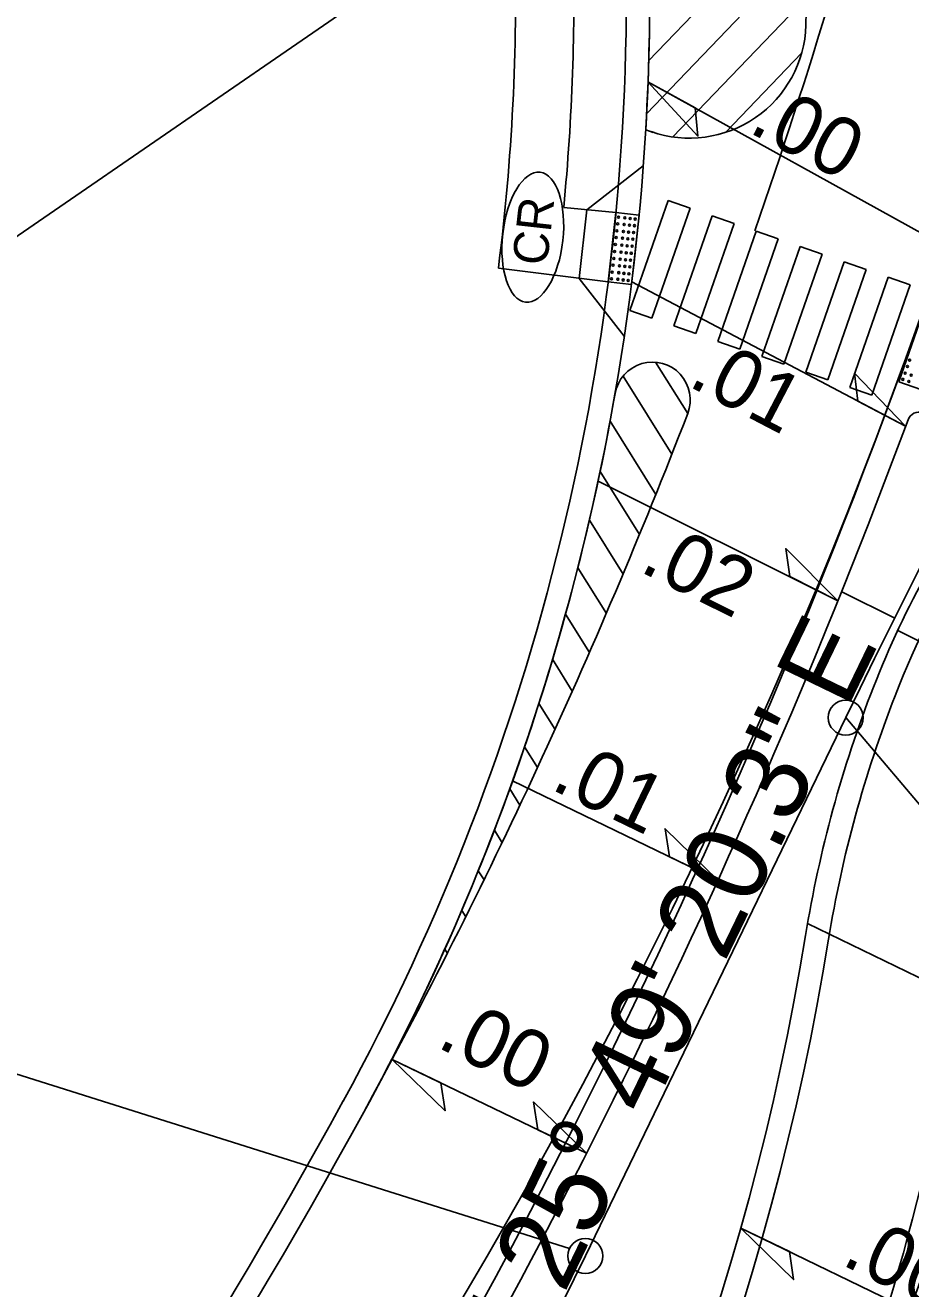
# Model space of a CAD drawing. Extents: x 2010838 to 2015151, y 441905 to 447792.
# Drawn here: x 2011817.1 to 2011893.1, y 444822.7 to 444931.1 of the extents above; entities that cross this region are included whole.
import ezdxf

# ---------------------------------------------------------------- set-up
doc = ezdxf.new("R2010")
doc.units = 0
for name, color, linetype in [('A-Wall-Blow', 7, 'Continuous'), ('A-Wall-Comp', 7, 'Continuous'), ('C-Alignment Geometry', 7, 'Continuous'), ('C-Building', 7, 'Continuous'), ('C-CURB STOPS', 7, 'Continuous'), ('CLRD', 7, 'Continuous'), ('Cont-2-Lidar', 7, 'Continuous'), ('Default_10ft_LIDAR_Contou', 7, 'Continuous'), ('HATCH', 7, 'Continuous'), ('S-overhead electric', 7, 'Continuous'), ('TEXT-LG', 7, 'Continuous'), ('TEXT-MED', 7, 'Continuous'), ('X4', 7, 'Continuous')]:
    doc.layers.add(name, color=color, linetype=linetype)

msp = doc.modelspace()

# ---------------------------------------------------------------- linework, layer by layer
at = {"layer": 'A-Wall-Blow'}
for p, q in [((2011897.95, 444911.04), (2011870.53, 444926.22)), ((2011892.64, 444896.68), (2011869.14, 444909.05)), ((2011866.25, 444891.98), (2011886.83, 444881.71)), ((2011891.96, 444879.15), (2011923.13, 444863.6)), ((2011858.92, 444866.26), (2011876.53, 444857.74)), ((2011884.23, 444854.02), (2011912.5, 444840.34)), ((2011848.59, 444842.38), (2011865.25, 444834.32)), ((2011878.5, 444827.91), (2011902.65, 444816.22))]:
    msp.add_line(p, q, dxfattribs=at)
at = {"layer": 'A-Wall-Comp'}
for points in [[(2011870.53, 444926.22), (2011874.82, 444921.56), (2011874.58, 444923.98)], [(2011892.64, 444896.68), (2011888.26, 444901.24), (2011888.55, 444898.83)], [(2011886.83, 444881.71), (2011882.35, 444886.18), (2011882.69, 444883.78)], [(2011876.53, 444857.74), (2011872, 444862.16), (2011872.37, 444859.76)], [(2011848.59, 444842.38), (2011853.12, 444837.97), (2011852.75, 444840.36)], [(2011865.25, 444834.32), (2011860.72, 444838.73), (2011861.09, 444836.33)], [(2011878.5, 444827.91), (2011883.03, 444823.49), (2011882.66, 444825.89)]]:
    msp.add_lwpolyline(points, close=True, dxfattribs=at)
at = {"layer": 'C-Alignment Geometry'}
for p, q in [((2011870.59, 444928.01), (2011882.99, 444940.93)), ((2011870.41, 444923.48), (2011883.72, 444937.35)), ((2011872.66, 444921.49), (2011884.08, 444933.39)), ((2011877.2, 444921.89), (2011883.71, 444928.67)), ((2011870.34, 444922.11), (2011870.98, 444921.88)), ((2011873.94, 444897.76), (2011871.19, 444902.17)), ((2011872.58, 444894.27), (2011868.39, 444900.98)), ((2011871.2, 444890.82), (2011867.28, 444897.1)), ((2011869.81, 444887.39), (2011866.43, 444892.8)), ((2011868.39, 444883.99), (2011865.5, 444888.62)), ((2011866.96, 444880.62), (2011864.51, 444884.54)), ((2011865.51, 444877.28), (2011863.46, 444880.57)), ((2011864.04, 444873.96), (2011862.34, 444876.69)), ((2011862.56, 444870.67), (2011861.17, 444872.9)), ((2011861.06, 444867.41), (2011859.95, 444869.19)), ((2011859.55, 444864.17), (2011858.67, 444865.57)), ((2011858.01, 444860.96), (2011857.35, 444862.03)), ((2011856.47, 444857.77), (2011855.97, 444858.56)), ((2011854.9, 444854.61), (2011854.56, 444855.16)), ((2011853.33, 444851.47), (2011853.1, 444851.84))]:
    msp.add_line(p, q, dxfattribs=at)
for centre, radius, start, end in [((2011849.1, 444932.2), 35, 358.1503, 56.9341), ((2011670.68, 444933.83), 200, 356.639, 1.3736), ((2011874.09, 444931.39), 10, 250.8378, 358.1503), ((2011870.91, 444898.93), 3.25, 338.8939, 170.1114), ((2011670.68, 444933.83), 200, 331.3204, 350.1114), ((2011407.48, 445077.81), 500, 331.3204, 338.8939), ((2011610.55, 444921.96), 300, 327.6618, 346.3627), ((2011662.93, 444888.8), 238, 327.6618, 350.8051)]:
    msp.add_arc(centre, radius, start, end, dxfattribs=at)
at = {"layer": 'C-Building'}
msp.add_line((2011891.7, 444880.22), (2011887.22, 444882.46), dxfattribs=at)
at = {"layer": 'C-CURB STOPS'}
for centre, radius, start, end in [((2011893.78, 444896.89), 1, 70.782, 159.5904), ((2011328.64, 445107.17), 602, 316.13249, 339.59044), ((2011966.23, 444844.41), 82, 143.1452, 158.6236), ((2011986.72, 444836.39), 104, 158.6236, 170.8051), ((2011662.93, 444888.8), 224, 304.0474, 350.8051)]:
    msp.add_arc(centre, radius, start, end, dxfattribs=at)
at = {"layer": 'CLRD'}
msp.add_line((2011865.16, 444825.52), (2011887.5, 444871.69), dxfattribs=at)
for centre, radius, start, end in [((2012535.6, 444558.07), 720, 139.84446, 154.1777), ((2011505.1, 444999.75), 400, 314.169, 334.1777)]:
    msp.add_arc(centre, radius, start, end, dxfattribs=at)
at = {"layer": 'Default_10ft_LIDAR_Contou'}
for p, q in [((2011917.67, 444982.63), (2011806.71, 444906.31)), ((2011863.81, 444826.17), (2011708.02, 444875.19)), ((2011887.5, 444871.69), (2011991.38, 444748.94))]:
    msp.add_line(p, q, dxfattribs=at)
for centre in [(2011887.5, 444871.69), (2011865.16, 444825.52)]:
    msp.add_circle(centre, 1.5, dxfattribs=at)
at = {"layer": 'HATCH'}
for p, q in [((2011872.26, 444916.04), (2011868.97, 444906.6)), ((2011874.15, 444915.38), (2011872.26, 444916.04)), ((2011870.86, 444905.94), (2011874.15, 444915.38)), ((2011876.04, 444914.72), (2011872.75, 444905.28)), ((2011874.63, 444904.62), (2011877.93, 444914.06)), ((2011877.93, 444914.06), (2011876.04, 444914.72)), ((2011879.81, 444913.41), (2011876.52, 444903.96)), ((2011878.41, 444903.3), (2011881.7, 444912.75)), ((2011881.7, 444912.75), (2011879.81, 444913.41)), ((2011883.59, 444912.09), (2011880.3, 444902.65)), ((2011885.48, 444911.43), (2011883.59, 444912.09)), ((2011882.19, 444901.99), (2011885.48, 444911.43)), ((2011887.37, 444910.77), (2011884.08, 444901.33)), ((2011889.26, 444910.11), (2011887.37, 444910.77)), ((2011885.97, 444900.67), (2011889.26, 444910.11)), ((2011891.15, 444909.46), (2011887.85, 444900.01)), ((2011893.03, 444908.8), (2011891.15, 444909.46)), ((2011889.74, 444899.35), (2011893.03, 444908.8)), ((2011868.97, 444906.6), (2011870.86, 444905.94)), ((2011872.75, 444905.28), (2011874.63, 444904.62)), ((2011876.52, 444903.96), (2011878.41, 444903.3)), ((2011880.3, 444902.65), (2011882.19, 444901.99)), ((2011884.08, 444901.33), (2011885.97, 444900.67)), ((2011887.85, 444900.01), (2011889.74, 444899.35))]:
    msp.add_line(p, q, dxfattribs=at)
for centre, radius, start, end in [((2011407.48, 445077.81), 500, 340.8089, 345.6791), ((2011441.41, 445066.15), 480, 314.169, 340.011)]:
    msp.add_arc(centre, radius, start, end, dxfattribs=at)
at = {"layer": 'S-overhead electric'}
for centre, radius, start, end in [((2011670.68, 444933.83), 200, 331.3204, 1.3736), ((2011328.64, 445107.17), 600, 314.56735, 343.62875), ((2011966.23, 444844.41), 80, 116.3467, 158.6236), ((2011986.72, 444836.39), 102, 158.6236, 170.8051), ((2011662.93, 444888.8), 226, 304.0474, 350.8051), ((2011629.97, 444941.31), 300, 303.2131, 341.328), ((2011407.48, 445077.81), 500, 314.169, 331.3204)]:
    msp.add_arc(centre, radius, start, end, dxfattribs=at)
at = {"layer": 'TEXT-LG'}
for p, q in [((2011870.13, 444919), (2011865.29, 444915.25)), ((2011867.78, 444915.01), (2011863.3, 444915.44)), ((2011865.29, 444915.25), (2011864.64, 444909.36)), ((2011867.78, 444915.01), (2011867.12, 444909.05)), ((2011867.78, 444915.01), (2011869.77, 444914.79)), ((2011869.77, 444914.79), (2011869.11, 444908.83)), ((2011867.12, 444909.05), (2011857.7, 444910.24)), ((2011868.5, 444904.39), (2011864.64, 444909.36)), ((2011869.11, 444908.83), (2011867.12, 444909.05)), ((2011894.04, 444906.15), (2011892.06, 444900.49)), ((2011893.95, 444899.83), (2011892.06, 444900.49))]:
    msp.add_line(p, q, dxfattribs=at)
for centre in [(2011867.93, 444914.03), (2011868, 444914.6), (2011868.48, 444913.98), (2011868.55, 444914.55), (2011868.94, 444913.92), (2011869.01, 444914.49), (2011869.37, 444913.88), (2011869.43, 444914.45), (2011867.8, 444912.86), (2011867.86, 444913.43), (2011868.35, 444912.81), (2011868.42, 444913.38), (2011868.81, 444912.75), (2011868.87, 444913.32), (2011869.23, 444912.72), (2011869.3, 444913.29), (2011867.67, 444911.66), (2011867.73, 444912.27), (2011868.22, 444911.61), (2011868.28, 444912.21), (2011868.67, 444911.55), (2011868.74, 444912.16), (2011869.1, 444911.51), (2011869.17, 444912.12), (2011867.53, 444910.5), (2011867.6, 444911.07), (2011868.08, 444910.44), (2011868.15, 444911.01), (2011868.54, 444910.39), (2011868.61, 444910.96), (2011868.97, 444910.35), (2011869.03, 444910.92), (2011867.4, 444909.33), (2011867.46, 444909.9), (2011867.95, 444909.28), (2011868.02, 444909.85), (2011868.47, 444909.79), (2011868.9, 444909.75), (2011868.41, 444909.22), (2011868.84, 444909.18), (2011892.79, 444901.81), (2011892.98, 444902.35), (2011892.4, 444900.7), (2011892.59, 444901.24), (2011893.11, 444901.06), (2011892.92, 444900.52)]:
    msp.add_circle(centre, 0.0869, dxfattribs=at)
for centre, radius, start, end in [((2011670.68, 444933.83), 188.5, 352.81, 1.3736), ((2011670.68, 444933.83), 193.5, 354.5462, 1.3736), ((2011629.97, 444941.31), 306.5, 303.2131, 341.328), ((2011629.97, 444941.31), 311.5, 303.2131, 341.328)]:
    msp.add_arc(centre, radius, start, end, dxfattribs=at)
at = {"layer": 'TEXT-MED'}
for centre, radius, start, end in [((2011670.68, 444933.83), 198, 331.3204, 1.3736), ((2011629.97, 444941.31), 302, 303.2131, 341.328), ((2011407.48, 445077.81), 498, 314.169, 331.3204)]:
    msp.add_arc(centre, radius, start, end, dxfattribs=at)
at = {"layer": 'X4'}
msp.add_ellipse((2011860.65, 444912.89), major_axis=(0.62, 5.57), ratio=0.462467, dxfattribs=at)

# ---------------------------------------------------------------- texts
at = {"layer": 'A-Wall-Blow'}
for s, rotation, p in [('.00', 332.4532, (2011879.03, 444921.96)), ('.01', 332.4532, (2011873.84, 444900.2)), ('.02', 333.4877, (2011869.68, 444884.29)), ('.01', 334.1777, (2011862.06, 444865.61)), ('.00', 334.1777, (2011852.29, 444843.48)), ('.00', 334.1777, (2011887, 444824.83))]:
    msp.add_text(s, height=5, rotation=rotation, dxfattribs=at).set_placement(p)
at = {"layer": 'Cont-2-Lidar'}
msp.add_text('N 25%%d 49\' 20.3" E', height=7, rotation=64.1777, dxfattribs=at).set_placement((2011859.25, 444813.77))
at = {"layer": 'X4'}
msp.add_text('CR', height=3, rotation=83.6545, dxfattribs=at).set_placement((2011861.86, 444910.38))

doc.saveas('drawing.dxf')
